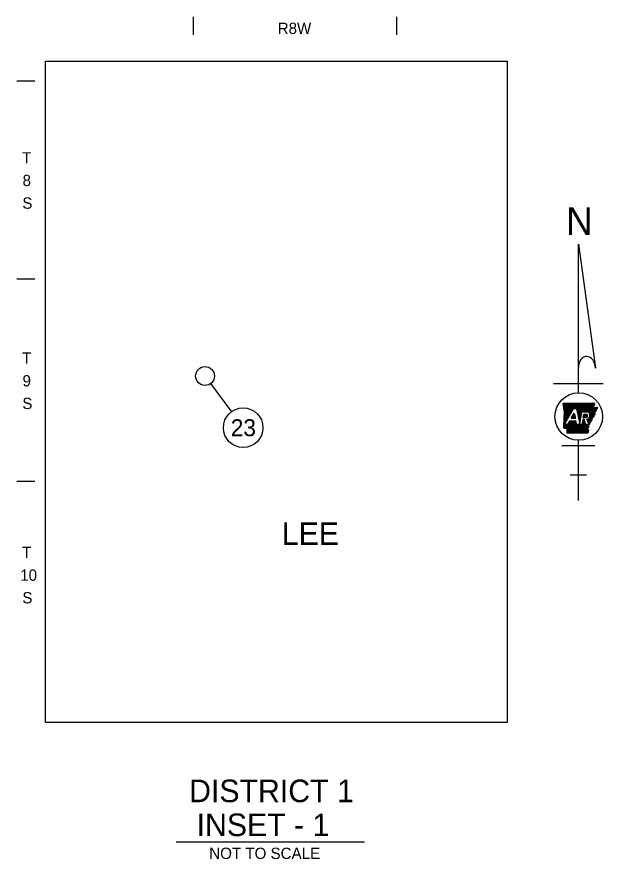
# Model space of a CAD drawing. Extents: x -33639 to 34530, y -17264 to 5867.
# Drawn here: x 25930 to 29041, y -11581 to -7113 of the extents above; entities that cross this region are included whole.
import ezdxf

# ---------------------------------------------------------------- set-up
doc = ezdxf.new("R2010")
doc.units = 0
for name, color, linetype in [('2', 7, 'Continuous'), ('Default', 7, 'Continuous'), ('R_Annotation', 7, 'Continuous'), ('R_No Plot', 7, 'Continuous')]:
    doc.layers.add(name, color=color, linetype=linetype)

msp = doc.modelspace()

# ---------------------------------------------------------------- linework, layer by layer
at = {"layer": 'Default'}
for p, q in [((26865.5, -7113.3), (26865.5, -7208.3)), ((27945, -7113.3), (27945, -7208.3)), ((26024.7, -7455.3), (25929.7, -7455.3)), ((26024.7, -8504.5), (25929.7, -8504.5)), ((26024.7, -9578.9), (25929.7, -9578.9))]:
    msp.add_line(p, q, dxfattribs=at)
at = {"layer": 'R_Annotation'}
for p, q in [((28909.1, -8319.6), (29000, -8976.6)), ((28909.1, -9107.5), (28909.1, -8319.6)), ((26958, -9058.7), (27068.2, -9208.1)), ((28777.5, -9058.8), (29040.6, -9058.8)), ((28829.3, -9163.9), (28830.3, -9162.9)), ((28829.6, -9167), (28833.8, -9162.9)), ((28830, -9170.1), (28837.3, -9162.9)), ((28830.4, -9173.2), (28840.8, -9162.9)), ((28830.8, -9176.3), (28844.3, -9162.9)), ((28831.2, -9179.4), (28847.7, -9162.9)), ((28831.6, -9182.5), (28851.2, -9162.9)), ((28832, -9185.6), (28854.7, -9162.9)), ((28832.3, -9188.7), (28858.2, -9162.9)), ((28832.7, -9191.8), (28861.7, -9162.9)), ((28833.1, -9194.9), (28865.1, -9162.9)), ((28833.5, -9198), (28868.6, -9162.9)), ((28833.9, -9201.1), (28872.1, -9162.9)), ((28834.1, -9246.1), (28876.7, -9203.6)), ((28834.3, -9204.2), (28875.6, -9162.9)), ((28834.3, -9242.5), (28881.3, -9195.5)), ((28834.4, -9238.9), (28910.5, -9162.8)), ((28834.5, -9235.3), (28907, -9162.8)), ((28834.6, -9231.7), (28903.5, -9162.8)), ((28834.7, -9228.1), (28900, -9162.8)), ((28834.7, -9207.3), (28879.1, -9162.9)), ((28834.9, -9224.5), (28896.5, -9162.8)), ((28835, -9220.9), (28893, -9162.9)), ((28835, -9210.4), (28882.6, -9162.9)), ((28835.1, -9217.3), (28889.5, -9162.9)), ((28835.2, -9213.7), (28886.1, -9162.9)), ((28835.4, -9276.5), (28884, -9190.7)), ((28884, -9190.7), (28898.4, -9190.7)), ((28886.1, -9190.7), (28914, -9162.8)), ((28889.6, -9190.7), (28917.5, -9162.8)), ((28893.1, -9190.7), (28921, -9162.8)), ((28896.6, -9190.7), (28924.5, -9162.7)), ((28898.7, -9192), (28928.1, -9162.7)), ((28899.3, -9194.9), (28931.6, -9162.6)), ((28900, -9197.7), (28935.1, -9162.6)), ((28900.6, -9200.6), (28938.7, -9162.5)), ((28901.2, -9203.5), (28942.2, -9162.4)), ((28901.8, -9206.3), (28945.7, -9162.4)), ((28902.4, -9209.2), (28949.3, -9162.3)), ((28903, -9212.1), (28952.8, -9162.3)), ((28903.6, -9214.9), (28956.4, -9162.2)), ((28904.2, -9217.8), (28959.9, -9162.2)), ((28904.9, -9220.7), (28963.4, -9162.1)), ((28905.5, -9223.6), (28967, -9162.1)), ((28906.1, -9226.4), (28970.5, -9162)), ((28906.7, -9229.3), (28974.1, -9161.9)), ((28930.9, -9208.6), (28977.7, -9161.8)), ((28934.4, -9208.6), (28981.2, -9161.7)), ((28937.9, -9208.6), (28984.8, -9161.7)), ((28941.3, -9208.6), (28988.3, -9161.6)), ((28944.8, -9208.6), (28991.9, -9161.5)), ((28948.3, -9208.6), (28992.7, -9164.2)), ((28951.8, -9208.6), (28994.4, -9166)), ((28955.3, -9208.6), (28994.8, -9169)), ((28958.8, -9208.6), (28986.9, -9180.5)), ((28961.9, -9208.9), (28986.2, -9184.6)), ((28963.8, -9210.5), (28989.9, -9184.5)), ((28965.5, -9212.3), (28993.5, -9184.3)), ((28967, -9214.2), (28997.2, -9184.1)), ((28968.3, -9216.4), (29000.9, -9183.9)), ((28969.4, -9218.9), (29004.5, -9183.7)), ((28970, -9232.2), (29001.6, -9200.6)), ((28970.2, -9221.5), (29007.9, -9183.9)), ((28970.7, -9224.5), (29009.5, -9185.7)), ((28970.7, -9228), (29001.2, -9197.5)), ((28997.7, -9208), (29002, -9203.7)), ((29007.9, -9190.8), (29011.1, -9187.6)), ((28833.5, -9264.1), (28854, -9243.7)), ((28833.7, -9260.5), (28858.5, -9235.7)), ((28833.8, -9256.9), (28863.1, -9227.6)), ((28833.9, -9253.3), (28867.6, -9219.6)), ((28834, -9249.7), (28872.2, -9211.6)), ((28871.2, -9242.8), (28887.1, -9214.7)), ((28871.2, -9242.8), (28893.1, -9242.8)), ((28871.3, -9242.8), (28889.2, -9224.9)), ((28874.8, -9242.8), (28889.8, -9227.8)), ((28875.5, -9235.2), (28888.6, -9222)), ((28878.3, -9242.8), (28890.5, -9230.6)), ((28880, -9227.1), (28888, -9219.2)), ((28881.8, -9242.8), (28891.1, -9233.5)), ((28884.6, -9219.1), (28887.4, -9216.3)), ((28885.3, -9242.8), (28891.7, -9236.4)), ((28888.7, -9242.8), (28892.3, -9239.3)), ((28892.2, -9242.8), (28892.9, -9242.1)), ((28907.3, -9232.2), (28927.1, -9212.4)), ((28907.9, -9235), (28926.3, -9216.6)), ((28908.5, -9237.9), (28925.6, -9220.8)), ((28909.2, -9240.8), (28924.9, -9225.1)), ((28909.8, -9243.6), (28924.1, -9229.3)), ((28910.4, -9246.5), (28923.4, -9233.5)), ((28911, -9249.4), (28922.7, -9237.7)), ((28911.6, -9252.2), (28921.9, -9241.9)), ((28912.2, -9255.1), (28921.2, -9246.1)), ((28927.7, -9208.6), (28961.5, -9208.6)), ((28935.1, -9239), (28953.4, -9220.7)), ((28935.1, -9239), (28949.5, -9239)), ((28935.8, -9234.8), (28949.9, -9220.7)), ((28936.5, -9230.6), (28946.4, -9220.7)), ((28937.3, -9226.4), (28943, -9220.7)), ((28938, -9222.2), (28939.5, -9220.7)), ((28938.3, -9220.7), (28954.1, -9220.7)), ((28938.6, -9239), (28955.3, -9222.2)), ((28942.1, -9239), (28956.5, -9224.5)), ((28945.5, -9239), (28957.2, -9227.4)), ((28949, -9239), (28956.9, -9231.2)), ((28953.4, -9247.7), (28964, -9276.5)), ((28953.7, -9248.5), (28954.8, -9247.4)), ((28954.6, -9251), (28961.3, -9244.4)), ((28955.6, -9253.6), (28994.2, -9215)), ((28956.5, -9256.1), (28994.8, -9217.8)), ((28957.5, -9258.6), (28995.5, -9220.6)), ((28958.4, -9261.2), (28996.1, -9223.4)), ((28959.3, -9263.7), (28980.2, -9242.8)), ((28960.3, -9266.3), (28979.8, -9246.7)), ((28966.9, -9238.7), (28993.5, -9212.1)), ((28984.2, -9238.8), (28989.1, -9233.9)), ((28832.6, -9292.9), (28849.1, -9276.5)), ((28832.7, -9289.4), (28845.6, -9276.5)), ((28832.8, -9285.8), (28842.1, -9276.5)), ((28833, -9282.2), (28838.6, -9276.5)), ((28833.1, -9278.5), (28835.8, -9275.8)), ((28833.2, -9274.9), (28840.3, -9267.8)), ((28833.3, -9271.3), (28844.9, -9259.8)), ((28833.4, -9267.7), (28849.4, -9251.7)), ((28833.9, -9295.1), (28870.5, -9258.5)), ((28852.1, -9276.5), (28835.4, -9276.5)), ((28836, -9296.5), (28874, -9258.5)), ((28838.5, -9297.5), (28877.5, -9258.5)), ((28842.7, -9296.8), (28881, -9258.5)), ((28846.2, -9296.8), (28884.5, -9258.5)), ((28848.9, -9297.5), (28888, -9258.5)), ((28849, -9304.4), (28894.9, -9258.5)), ((28849, -9300.9), (28891.4, -9258.5)), ((28849.1, -9307.8), (28896.8, -9260.1)), ((28849.1, -9311.3), (28897.4, -9263)), ((28849.1, -9314.8), (28898, -9265.9)), ((28849.1, -9318.3), (28898.6, -9268.7)), ((28849.1, -9321.7), (28899.2, -9271.6)), ((28862.3, -9258.5), (28852.1, -9276.5)), ((28852.6, -9321.7), (28899.8, -9274.5)), ((28856, -9269.5), (28867.1, -9258.5)), ((28856.1, -9321.7), (28901.3, -9276.5)), ((28859.6, -9321.7), (28904.8, -9276.5)), ((28860.6, -9261.5), (28863.6, -9258.5)), ((28896.4, -9258.5), (28862.3, -9258.5)), ((28863, -9321.7), (28908.3, -9276.5)), ((28866.5, -9321.7), (28911.8, -9276.5)), ((28870, -9321.7), (28915.2, -9276.5)), ((28873.5, -9321.7), (28918.7, -9276.5)), ((28877, -9321.7), (28922.2, -9276.5)), ((28880.4, -9321.7), (28925.7, -9276.5)), ((28883.9, -9321.7), (28943.8, -9261.8)), ((28887.4, -9321.8), (28944.8, -9264.4)), ((28890.9, -9321.8), (28945.7, -9266.9)), ((28894.3, -9321.8), (28946.6, -9269.5)), ((28897.8, -9321.8), (28947.6, -9272)), ((28928.5, -9276.5), (28900.3, -9276.5)), ((28901.3, -9321.8), (28948.5, -9274.6)), ((28904.8, -9321.8), (28950.1, -9276.5)), ((28908.2, -9321.8), (28953.5, -9276.5)), ((28911.7, -9321.8), (28957, -9276.5)), ((28912.8, -9258), (28920.5, -9250.4)), ((28913.5, -9260.9), (28919.7, -9254.6)), ((28914.1, -9263.7), (28919, -9258.8)), ((28914.7, -9266.6), (28918.3, -9263)), ((28915.2, -9321.8), (28960.5, -9276.5)), ((28915.3, -9269.5), (28917.5, -9267.2)), ((28915.9, -9272.3), (28916.8, -9271.5)), ((28918.7, -9321.8), (28961.7, -9278.8)), ((28922.2, -9321.8), (28961.8, -9282.1)), ((28925.6, -9321.8), (28962, -9285.5)), ((28929.1, -9273), (28942.9, -9259.3)), ((28929.1, -9321.8), (28962.1, -9288.8)), ((28929.9, -9268.8), (28941.9, -9256.8)), ((28930.6, -9264.6), (28941, -9254.2)), ((28931.3, -9260.4), (28940.1, -9251.7)), ((28932.1, -9256.2), (28939, -9249.2)), ((28932.8, -9251.9), (28935.6, -9249.2)), ((28939.1, -9249.2), (28933.3, -9249.2)), ((28949.2, -9276.5), (28939.1, -9249.2)), ((28964, -9276.5), (28949.2, -9276.5)), ((28961.2, -9268.8), (28979.4, -9250.6)), ((28962.2, -9271.4), (28972.8, -9260.7)), ((28963.1, -9273.9), (28971.3, -9265.7)), ((28932.6, -9321.8), (28956.4, -9298)), ((28936.1, -9321.8), (28957.5, -9300.4)), ((28939.5, -9321.8), (28958.6, -9302.8)), ((28943, -9321.8), (28959.7, -9305.2)), ((28946.5, -9321.8), (28960.7, -9307.6)), ((28950, -9321.9), (28961.6, -9310.2)), ((28953.5, -9321.9), (28960.1, -9315.3)), ((28956.9, -9321.9), (28958.5, -9320.3)), ((28909.1, -9679.3), (28909.1, -9359.6)), ((28821.4, -9386.7), (28996.8, -9386.7)), ((28865.2, -9542.5), (28952.9, -9542.5)), ((26774.6, -11489.8), (27774.6, -11489.8))]:
    msp.add_line(p, q, dxfattribs=at)
for points in [[(28829.1, -9162.9), (28877.2, -9162.9), (28919.4, -9162.8), (28969.1, -9162), (28992.1, -9161.5)], [(28829.1, -9162.9), (28877.2, -9162.9), (28919.3, -9162.8), (28969.1, -9162), (28992.1, -9161.5)], [(28834.4, -9237.6), (28835.3, -9212.2), (28829.1, -9162.9)], [(28832.6, -9292.9), (28835.3, -9212.2), (28829.1, -9162.9)], [(28898.4, -9190.7), (28916.3, -9274.2), (28927.7, -9208.6)], [(29007.2, -9183.6), (29011.4, -9187.9), (29001, -9196.4), (29002.1, -9205), (28993.3, -9210.9), (28996.3, -9224.1), (28989.4, -9230.4), (28988.8, -9237.2), (28980.5, -9240.2), (28979.2, -9253), (28973.2, -9259.4), (28970.3, -9269.1), (28961.6, -9277.1), (28962.3, -9291.1), (28956.3, -9297.8), (28961.7, -9309.9), (28958, -9321.9)], [(28985, -9184.7), (29007.6, -9183.5)], [(28985, -9184.7), (29007.6, -9183.5)], [(28832.6, -9292.9), (28834.4, -9237.6)], [(28887.1, -9214.7), (28893.1, -9242.8)], [(28935.1, -9239), (28938.3, -9220.7)], [(28900.3, -9276.5), (28896.4, -9258.5)], [(28933.3, -9249.2), (28928.5, -9276.5)], [(28958, -9321.9), (28849.1, -9321.7), (28849, -9297.6)], [(28958, -9321.9), (28849.1, -9321.7), (28849, -9297.6)]]:
    msp.add_lwpolyline(points, dxfattribs=at)
for centre, radius in [((26928.4, -9018.5), 50), ((27130.6, -9292.6), 105)]:
    msp.add_circle(centre, radius, dxfattribs=at)
for centre, major_axis, ratio, start_param, end_param in [((28954.5, -8978.1), (-1.9, 63.2), 0.719778, 4.712385, 7.768526), ((28946.1, -9228.4), (-11.1, 0), 0.999987, 1.887169, 3.90762), ((28948.9, -9226.4), (-21.8, 0), 0.999987, 1.777838, 4.099264)]:
    msp.add_ellipse(centre, major_axis=major_axis, ratio=ratio, start_param=start_param, end_param=end_param, dxfattribs=at)
msp.add_ellipse((28911.1, -9233.5), major_axis=(126, 0), ratio=0.999976, dxfattribs=at)
for points in [[(28992.1, -9161.5), (28992.3, -9162.8), (28992.7, -9163.5), (28992.7, -9164.7), (28993.3, -9165.3), (28994.1, -9165.8), (28994.9, -9166.7), (28995.1, -9167.7), (28994.8, -9168.7), (28994.8, -9169.9), (28994.7, -9170.9), (28994.5, -9171.8), (28993.8, -9172.6), (28993.1, -9173.1), (28992.5, -9173.7), (28992, -9174.4), (28991.3, -9175.1), (28990.5, -9175.8), (28989.8, -9176.5), (28989.2, -9177.3), (28988.9, -9178.2), (28988.2, -9178.9), (28987.7, -9179.5), (28987, -9180.3), (28986.6, -9181.1), (28986, -9182), (28985.8, -9182.9), (28985.4, -9183.6), (28985.3, -9183.7)], [(28992.1, -9161.5), (28992.3, -9162.8), (28992.7, -9163.5), (28992.8, -9164.7), (28993.3, -9165.3), (28994.1, -9165.8), (28994.9, -9166.7), (28995.1, -9167.7), (28994.8, -9168.7), (28994.8, -9169.9), (28994.7, -9170.9), (28994.5, -9171.8), (28993.8, -9172.5), (28993.1, -9173.1), (28992.5, -9173.7), (28992, -9174.4), (28991.2, -9175.1), (28990.5, -9175.8), (28989.8, -9176.5), (28989.2, -9177.3), (28988.9, -9178.2), (28988.2, -9178.9), (28987.7, -9179.5), (28987, -9180.3), (28986.6, -9181.1), (28986, -9182), (28985.8, -9182.9), (28985.4, -9183.6), (28985.3, -9183.7)], [(29007.2, -9183.6), (29007.6, -9183.5), (29008.6, -9184.6), (29009, -9185.5), (29009.7, -9186), (29010.4, -9186.3), (29011, -9187), (29011.4, -9187.7), (29011.2, -9188.4), (29010.3, -9188.4), (29009.4, -9188.6), (29008.5, -9188.5), (29007.8, -9189.1), (29008.4, -9189.9), (29009.3, -9190.7), (29009.6, -9191.5), (29009.1, -9192.2), (29008.1, -9192.7), (29007.2, -9193), (29006.4, -9193.7), (29006, -9194.4), (29005.1, -9194.7), (29004.1, -9195), (29003.3, -9195.1), (29002.3, -9195.3), (29001.4, -9195.7), (29001, -9196.5), (29001.1, -9197.6), (29001.1, -9198.7), (29002.1, -9199.1), (29002.9, -9199.2), (29003.8, -9199.6), (29003.7, -9200.2), (29003.1, -9201.1), (29002.3, -9201.7), (29001.6, -9202.1), (29000.9, -9202.7), (29001.1, -9203.3), (29001.8, -9203.7), (29002.2, -9204.4), (29002.1, -9205), (29001.4, -9205.5), (29000.7, -9205.3), (29000.1, -9204.5), (28999.5, -9204.3), (28998.9, -9204), (28998.2, -9204.4), (28998.2, -9205.3), (28998, -9206.2), (28998.2, -9206.9), (28998.4, -9207.8), (28998.4, -9208.6), (28998.2, -9209.6), (28997.7, -9210.6), (28997.1, -9210.9), (28996.8, -9209.8), (28996.7, -9208.9), (28996.4, -9208.3), (28995.9, -9208.3), (28995.3, -9208.8), (28994.6, -9209.5), (28993.8, -9210.2), (28993.2, -9210.9), (28993.5, -9211.9), (28994.2, -9212.1), (28994.7, -9211.9), (28994.9, -9211.3), (28995.4, -9211.2), (28995.9, -9212.2)], [(28983, -9241.6), (28982, -9242.4), (28981.5, -9243.2), (28978.9, -9243), (28978.9, -9243.9), (28978, -9244.4), (28977.2, -9245), (28977.6, -9245.7), (28978.5, -9246.4), (28979.4, -9246.9), (28980, -9247.4), (28980.1, -9248.6), (28980.3, -9249.4), (28980.6, -9250.5), (28980.7, -9251.2), (28980.2, -9252.1), (28979.5, -9252.3), (28978.9, -9252), (28978.1, -9252), (28977.5, -9252.6), (28977, -9253.4), (28976.6, -9254.3), (28976.3, -9255), (28975.9, -9255.7), (28975.3, -9256.6), (28974.5, -9256.8), (28973.5, -9257), (28973, -9257.6), (28973.1, -9258.8), (28973.6, -9259.5), (28974, -9260.4), (28974.3, -9261.2), (28974.2, -9262.2), (28973.8, -9263), (28973.2, -9263.4), (28973, -9264.4), (28972.6, -9265.1), (28972.2, -9265.3), (28971.5, -9265.3), (28970.8, -9265.1), (28970.1, -9265.2), (28969.5, -9265.5), (28968.8, -9265.3), (28968.2, -9264.6), (28967.7, -9264), (28967.1, -9263.8), (28966.4, -9264.2), (28966.3, -9265.2), (28966.6, -9266.2), (28966.9, -9267.5), (28966.6, -9268.3), (28966.5, -9269.7)], [(28995.9, -9212.2), (28996, -9213), (28995.5, -9213.9), (28995.3, -9214.9), (28995.4, -9215.8), (28994.5, -9216.3), (28993.7, -9216.9), (28994.1, -9217.6), (28995, -9218.2), (28995.9, -9218.7), (28996.5, -9219.3), (28996.6, -9220.5), (28996.8, -9221.3), (28997.1, -9222.3), (28997.2, -9223.1), (28996.7, -9223.9), (28996, -9224.1), (28995.4, -9223.9), (28994.6, -9223.9), (28994, -9224.4), (28993.5, -9225.3), (28993.1, -9226.1), (28992.7, -9226.8), (28992.4, -9227.6), (28991.8, -9228.5), (28991, -9228.6), (28990, -9228.9), (28989.5, -9229.5), (28989.6, -9230.6), (28990.1, -9231.4), (28990.5, -9232.3), (28990.8, -9233.1), (28990.7, -9234.1), (28990.2, -9234.9), (28989.7, -9235.3), (28989.5, -9236.2), (28989.1, -9237), (28988.7, -9237.2), (28988, -9237.2), (28987.2, -9237), (28986.6, -9237.1), (28986, -9237.4), (28985.3, -9237.2), (28984.7, -9236.5), (28984.1, -9235.9), (28983.5, -9235.7), (28982.9, -9236), (28982.8, -9237), (28983.1, -9238), (28983.4, -9239.4), (28983.1, -9240.2), (28983, -9241.6)], [(28849, -9297.6), (28849.2, -9297.7), (28848.6, -9297.3), (28847.8, -9296.9), (28846.9, -9296.9), (28845.8, -9296.7), (28844.9, -9296.6), (28844, -9296), (28843, -9296.7), (28841.8, -9297.1), (28841.2, -9296.6), (28840.3, -9297), (28839.7, -9296.8), (28838.7, -9297.5), (28837.7, -9297.2), (28837, -9297.4), (28836.1, -9297.4), (28835.9, -9296.4), (28835.1, -9296.3), (28834.3, -9295.8), (28833.8, -9294.8), (28833.4, -9294), (28832.6, -9292.9)], [(28849, -9297.6), (28849.1, -9297.7), (28848.6, -9297.3), (28847.8, -9296.9), (28846.9, -9296.9), (28845.8, -9296.7), (28844.9, -9296.6), (28844, -9296), (28843, -9296.7), (28841.8, -9297.1), (28841.2, -9296.6), (28840.3, -9297), (28839.7, -9296.8), (28838.7, -9297.5), (28837.7, -9297.2), (28837, -9297.4), (28836.1, -9297.4), (28835.9, -9296.4), (28835.1, -9296.3), (28834.3, -9295.8), (28833.8, -9294.8), (28833.5, -9294), (28832.6, -9292.9)], [(28962.5, -9280.9), (28962.2, -9281.6), (28961.9, -9282.8), (28962, -9283.8), (28962.5, -9284.7), (28963.2, -9285.1), (28964, -9285.8), (28963.9, -9286.9), (28963.4, -9287.2), (28962.4, -9287), (28961.6, -9286.6), (28960.9, -9286.8), (28960, -9287.3), (28959.3, -9287.4), (28959.3, -9288.8), (28960.2, -9289.8), (28961, -9289.8), (28962, -9289.9), (28962.3, -9291), (28961.8, -9291.9), (28960.9, -9292.3), (28959.7, -9291.8), (28959, -9291.2), (28958.1, -9290.7), (28957.1, -9290.4), (28956.6, -9290.5), (28956.3, -9291.8), (28956.8, -9292.9), (28957.5, -9293.7), (28958.3, -9294.7), (28958.1, -9295.5), (28957.6, -9295.7), (28956.7, -9295.9), (28956.1, -9296.2), (28956, -9296.4), (28956.2, -9297.4), (28956.5, -9298.5), (28956.5, -9299.4), (28956.2, -9300.1), (28955.7, -9301.3), (28955.7, -9302.1), (28956.1, -9302.4), (28956.5, -9302.3), (28957.1, -9301.9), (28957.5, -9301.4), (28957.9, -9300.8), (28958.5, -9300.3), (28959.2, -9300.8), (28959.4, -9301.7), (28959, -9302.5), (28958.3, -9302.9), (28957.6, -9303.2), (28957, -9303.8), (28957.1, -9304.6), (28957.6, -9305), (28958.7, -9304.8), (28959.4, -9304.4), (28959.9, -9304.1), (28960.4, -9303.5), (28960.6, -9303), (28961, -9302.5), (28961.7, -9302.3), (28962, -9302.8), (28961.9, -9303.8), (28961.5, -9304.8), (28960.9, -9305.5), (28960.3, -9306.1), (28959.5, -9307.3), (28959.7, -9308.5), (28960, -9309.4), (28960.4, -9310.1), (28961.1, -9310), (28961.9, -9309.9), (28962.4, -9310.2), (28962.3, -9311.1), (28961.7, -9311.9), (28961.2, -9312.7), (28960.9, -9313.7), (28961, -9314.5), (28961, -9315.1), (28960.8, -9315.9), (28960.3, -9316.3), (28959.2, -9316.3), (28958.1, -9316.2), (28957.5, -9316.5), (28957.6, -9317.5), (28958.3, -9318.3), (28958.7, -9318.7), (28959.4, -9319.5), (28959.7, -9320.2), (28959.6, -9320.8), (28959.2, -9321.3), (28958, -9321.9)], [(28962.5, -9280.9), (28962.2, -9281.6), (28961.9, -9282.8), (28962, -9283.8), (28962.5, -9284.7), (28963.2, -9285.1), (28964, -9285.8), (28963.9, -9286.9), (28963.4, -9287.2), (28962.4, -9287), (28961.6, -9286.6), (28960.9, -9286.8), (28960, -9287.3), (28959.3, -9287.4), (28959.3, -9288.8), (28960.2, -9289.8), (28961, -9289.8), (28962, -9289.9), (28962.3, -9291), (28961.8, -9291.9), (28960.9, -9292.3), (28959.7, -9291.8), (28959, -9291.2), (28958.1, -9290.7), (28957.1, -9290.4), (28956.6, -9290.5), (28956.3, -9291.8), (28956.8, -9292.9), (28957.5, -9293.7), (28958.3, -9294.7), (28958.1, -9295.5), (28957.6, -9295.7), (28956.7, -9295.9), (28956.1, -9296.2), (28956, -9296.4), (28956.2, -9297.4), (28956.5, -9298.5), (28956.5, -9299.4), (28956.2, -9300.1), (28955.7, -9301.3), (28955.7, -9302.1), (28956.1, -9302.4), (28956.5, -9302.3), (28957.1, -9301.9), (28957.5, -9301.4), (28957.9, -9300.8), (28958.5, -9300.3), (28959.2, -9300.8), (28959.4, -9301.7), (28959, -9302.5), (28958.3, -9302.9), (28957.6, -9303.2), (28957, -9303.8), (28957.1, -9304.6), (28957.6, -9305), (28958.7, -9304.8), (28959.4, -9304.4), (28959.9, -9304.1), (28960.4, -9303.5), (28960.6, -9303), (28961, -9302.5), (28961.7, -9302.3), (28962, -9302.8), (28961.9, -9303.8), (28961.5, -9304.8), (28960.9, -9305.5), (28960.3, -9306.1), (28959.5, -9307.3), (28959.7, -9308.5), (28960, -9309.4), (28960.4, -9310.1), (28961.1, -9310), (28961.9, -9309.9), (28962.4, -9310.2), (28962.3, -9311.1), (28961.7, -9311.9), (28961.2, -9312.7), (28960.9, -9313.7), (28961, -9314.5), (28961, -9315.1), (28960.8, -9315.9), (28960.3, -9316.3), (28959.2, -9316.3), (28958.1, -9316.2), (28957.5, -9316.5), (28957.6, -9317.5), (28958.3, -9318.3), (28958.7, -9318.7), (28959.4, -9319.5), (28959.7, -9320.2), (28959.6, -9320.8), (28959.2, -9321.3), (28958, -9321.9)], [(28966.5, -9269.7), (28966.5, -9269.8), (28965.9, -9270.4), (28966.2, -9271.5), (28967.4, -9271.9), (28967.9, -9272.9), (28967.9, -9273.8), (28967.6, -9275), (28967, -9275.6), (28966, -9275.8), (28965.2, -9276), (28965.1, -9277.3), (28964.7, -9278), (28964.1, -9278.2), (28963.2, -9277.8), (28962.7, -9277.6), (28962, -9277.3), (28961.2, -9276.8), (28960.5, -9276.9), (28960.7, -9278.2), (28960.8, -9278.2), (28961.5, -9279.2), (28962.2, -9280), (28962.5, -9280.9)], [(28966.5, -9269.7), (28966.5, -9269.8), (28965.9, -9270.4), (28966.2, -9271.5), (28967.4, -9271.9), (28967.9, -9272.9), (28967.9, -9273.8), (28967.6, -9275), (28967, -9275.6), (28966, -9275.8), (28965.2, -9276), (28965.1, -9277.3), (28964.7, -9278), (28964.1, -9278.2), (28963.2, -9277.8), (28962.7, -9277.6), (28962, -9277.3), (28961.2, -9276.8), (28960.5, -9276.9), (28960.7, -9278.2), (28960.8, -9278.2), (28961.5, -9279.2), (28962.2, -9280), (28962.5, -9280.9)]]:
    msp.add_spline(points, degree=3, dxfattribs=at)
at = {"layer": 'R_No Plot'}
msp.add_lwpolyline([(26081.1, -7348.5), (28531.3, -7348.5), (28531.3, -10856.8), (26081.1, -10856.8)], close=True, dxfattribs=at)

# ---------------------------------------------------------------- texts
at = {"layer": '2'}
for s, height, p in [('R8W', 60, (27313.7, -7204.1)), ('T', 60, (25957.6, -7891.1)), ('8', 60, (25960.2, -8011.1)), ('S', 60, (25958.8, -8131.1)), ('T', 60, (25957.6, -8953.7)), ('9', 60, (25960, -9073.7)), ('S', 60, (25958.8, -9193.7)), ('LEE', 120, (27335.6, -9914.8)), ('T', 60, (25957.6, -9984.5)), ('10', 60, (25947.7, -10104.5)), ('S', 60, (25958.8, -10224.5))]:
    msp.add_text(s, height=height, dxfattribs=at).set_placement(p)
at = {"layer": 'R_Annotation'}
for s, height, p in [('N', 146.7, (28843.7, -8270)), ('23', 90, (27064.7, -9337.6)), ('STS 10-03-17', 3.644, (28899.1, -9358.5)), ('DISTRICT 1', 120, (26843.8, -11279.1)), ('INSET - 1', 120, (26883.5, -11459.1)), ('NOT TO SCALE', 60, (26950.6, -11580.4))]:
    msp.add_text(s, height=height, dxfattribs=at).set_placement(p)

doc.saveas('drawing.dxf')
